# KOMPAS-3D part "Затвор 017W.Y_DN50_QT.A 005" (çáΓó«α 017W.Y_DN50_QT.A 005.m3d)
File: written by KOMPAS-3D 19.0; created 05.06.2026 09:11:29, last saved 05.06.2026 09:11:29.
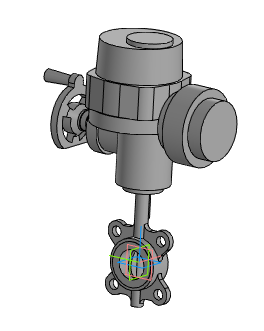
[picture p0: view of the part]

Document properties: Автор: Энергия; Полное имя файла: ..\..\..\3d для проектировщиков\x.x Тип 017W.Y(S) Затвор дисковый поворотный межфланцевый\Затвор 017W.Y(S)_DN32-DN1200_QT.A_MT903.A\Затвор 017W.Y_DN50_QT.A 005.a3d

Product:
- Part/product: Затвор 017W.Y_DN50_QT.A 005
    Масса: 38.1766

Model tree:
1. Операция без истории:1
